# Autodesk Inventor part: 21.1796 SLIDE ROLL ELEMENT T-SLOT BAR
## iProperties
Created: 2006-12
Part Number: 21.1796 SLIDE ROLL ELEMENT T-SLOT BAR
Material: Steel
Document SubType Name: Modeling
Designer: Andy Moles
Density: 7.85 g/cm^3
Mass: 52.7734 g
Surface Area: 40.4798 cm^2
Volume: 6.72272 cm^3
Author: Andy Moles
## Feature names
1. Extrusion1
2. Hole1
3. Extrusion2
